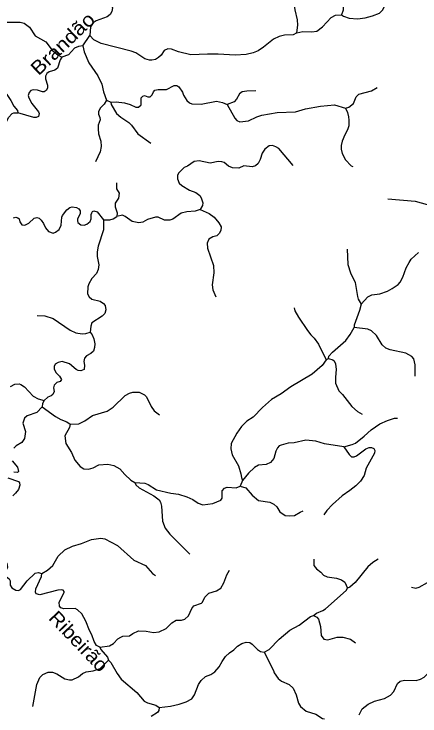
# Model space of a CAD drawing. Extents: x 577 to 602.9, y 7483.8 to 7511.6.
# Drawn here: x 592.922 to 595.283, y 7499.96 to 7504.044 of the extents above; entities that cross this region are included whole.
import ezdxf
from ezdxf.enums import TextEntityAlignment as Align

# ---------------------------------------------------------------- set-up
doc = ezdxf.new("R2010")
doc.units = 0
doc.header["$LTSCALE"] = 0.032
doc.layers.add('61', color=7, linetype='Continuous')
doc.layers.add('7', color=7, linetype='Continuous', lineweight=25)

msp = doc.modelspace()

# ---------------------------------------------------------------- linework, layer by layer
at = {"layer": '7'}
for p, q in [((593.3214, 7503.8597), (593.3623, 7503.9186)), ((593.4596, 7503.5434), (593.4857, 7503.5311)), ((594.738, 7502.032), (594.7511, 7502.0402)), ((594.2517, 7501.3306), (594.2378, 7501.2979))]:
    msp.add_line(p, q, dxfattribs=at)
for points in [[(594.568, 7503.9357), (594.5729, 7503.979), (594.5713, 7504.0101), (594.5565, 7504.0698), (594.5492, 7504.1303), (594.5492, 7504.1572), (594.5606, 7504.2439), (594.5588, 7504.2901)], [(594.7435, 7504.2553), (594.7478, 7504.2414), (594.7887, 7504.1907), (594.8312, 7504.127), (594.8361, 7504.1131), (594.8361, 7504.0673), (594.8263, 7504.0403)], [(593.4857, 7504.1793), (593.4808, 7504.1466), (593.4849, 7504.1049), (593.4939, 7504.0796), (593.4915, 7504.0583), (593.4808, 7504.0412), (593.4645, 7504.0289), (593.4007, 7504.0052), (593.3828, 7503.9938), (593.3664, 7503.9692), (593.3623, 7503.9186)], [(594.8263, 7504.0403), (594.8394, 7504.0322), (594.8721, 7504.0207), (594.9195, 7504.0158), (594.9653, 7504.0224), (595.0069, 7504.033), (595.0478, 7504.0502), (595.0682, 7504.0698), (595.0813, 7504.0984), (595.0862, 7504.1858)], [(592.7904, 7504.0254), (592.867, 7503.9978), (592.9569, 7503.9978), (592.9806, 7503.9913), (593.0125, 7503.9676), (593.0452, 7503.9177), (593.1073, 7503.8818), (593.1441, 7503.8344), (593.1792, 7503.8049), (593.2005, 7503.7943)], [(594.568, 7503.9357), (594.6023, 7503.9423), (594.6538, 7503.9414), (594.6841, 7503.9455), (594.7159, 7503.97), (594.7674, 7504.0248), (594.792, 7504.0371), (594.8263, 7504.0403)], [(594.568, 7503.9357), (594.5451, 7503.9243), (594.4944, 7503.921), (594.4634, 7503.9145), (594.4315, 7503.8973), (594.3735, 7503.8507), (594.3424, 7503.8311), (594.3138, 7503.818), (594.2729, 7503.8082), (594.2075, 7503.8049), (594.1094, 7503.8115), (594.0465, 7503.8115), (593.9509, 7503.8066), (593.8797, 7503.8246), (593.8372, 7503.8409), (593.8168, 7503.8425), (593.7955, 7503.8327), (593.7776, 7503.8057), (593.762, 7503.791), (593.744, 7503.7796), (593.7244, 7503.7755), (593.7105, 7503.7755), (593.6827, 7503.7837), (593.6304, 7503.818), (593.6035, 7503.8286), (593.4285, 7503.8728), (593.3868, 7503.8948), (593.3623, 7503.9186)], [(593.3214, 7503.8597), (593.2961, 7503.8554), (593.274, 7503.8466), (593.2389, 7503.8066), (593.2005, 7503.7943)], [(593.3214, 7503.8597), (593.3304, 7503.8254), (593.3566, 7503.7608), (593.4089, 7503.6856), (593.4334, 7503.6365), (593.4416, 7503.5916), (593.4596, 7503.5434)], [(592.3443, 7503.8202), (592.3937, 7503.7665), (592.4248, 7503.7428), (592.5081, 7503.7085), (592.5376, 7503.7003), (592.5923, 7503.6929), (592.7476, 7503.6807), (592.7738, 7503.6758), (592.7942, 7503.6668), (592.8269, 7503.6431), (592.8547, 7503.6137), (592.9029, 7503.5409), (592.9201, 7503.509), (592.9414, 7503.4837), (592.9446, 7503.4698)], [(593.2005, 7503.7943), (593.1898, 7503.7771), (593.1743, 7503.7289), (593.1588, 7503.7175), (593.1261, 7503.7077), (593.1138, 7503.6979), (593.1048, 7503.6831), (593.1048, 7503.6668), (593.1163, 7503.63), (593.1163, 7503.6137), (593.1089, 7503.5989), (593.0967, 7503.5916), (593.0877, 7503.5908), (593.0591, 7503.6014), (593.0354, 7503.603), (593.0198, 7503.5989), (593.0108, 7503.5883), (593.0051, 7503.5703), (593.0076, 7503.5564), (593.0255, 7503.5237), (593.0648, 7503.4755), (593.0681, 7503.4657), (593.0648, 7503.4477), (593.0509, 7503.442), (593.0378, 7503.442), (592.9446, 7503.4698)], [(593.4857, 7503.5311), (593.5152, 7503.5336), (593.565, 7503.5278), (593.5969, 7503.5188), (593.6296, 7503.5017), (593.6468, 7503.5017), (593.6623, 7503.5156), (593.6623, 7503.5573), (593.6705, 7503.5662), (593.6811, 7503.5695), (593.7007, 7503.563), (593.7138, 7503.563), (593.7261, 7503.5736), (593.7326, 7503.5924), (593.7416, 7503.6006), (593.7604, 7503.6047), (593.8094, 7503.6055), (593.8528, 7503.6284), (593.8683, 7503.6276), (593.8814, 7503.6202), (593.9018, 7503.5891), (593.9075, 7503.572), (593.9263, 7503.5417), (593.9435, 7503.527), (593.9566, 7503.5221), (594.0105, 7503.5205), (594.0988, 7503.5368), (594.134, 7503.5303), (594.1626, 7503.518)], [(594.3289, 7503.5981), (594.2754, 7503.5965), (594.25, 7503.5908), (594.2345, 7503.5793), (594.2157, 7503.5483), (594.2018, 7503.5336), (594.1626, 7503.518)], [(594.8508, 7503.496), (594.8704, 7503.5025), (594.8958, 7503.5237), (594.9121, 7503.563), (594.9277, 7503.5785), (595.0012, 7503.5981), (595.0346, 7503.6165)], [(593.4596, 7503.5434), (593.4465, 7503.5197), (593.4236, 7503.496), (593.4138, 7503.4747), (593.4138, 7503.4624), (593.422, 7503.4428), (593.4236, 7503.4289), (593.4122, 7503.397), (593.4105, 7503.3766), (593.413, 7503.348), (593.4277, 7503.3039), (593.4293, 7503.2728), (593.4236, 7503.2434), (593.3957, 7503.1849)], [(593.4857, 7503.5311), (593.4874, 7503.518), (593.5184, 7503.4657), (593.543, 7503.4436), (593.5904, 7503.4142), (593.6059, 7503.3987), (593.6419, 7503.348), (593.717, 7503.2932)], [(594.1626, 7503.518), (594.2059, 7503.4387), (594.219, 7503.424), (594.2361, 7503.4175), (594.286, 7503.4224), (594.335, 7503.4469), (594.3628, 7503.4559), (594.4527, 7503.4714), (594.559, 7503.4747), (594.6179, 7503.4935), (594.7045, 7503.509), (594.7854, 7503.5156), (594.8508, 7503.496)], [(594.8508, 7503.496), (594.8623, 7503.4706), (594.8672, 7503.4461), (594.8704, 7503.4273), (594.8688, 7503.3938), (594.8614, 7503.3701), (594.8459, 7503.3423), (594.8312, 7503.3047), (594.8255, 7503.2793), (594.8255, 7503.2581), (594.8304, 7503.2327), (594.8508, 7503.1968), (594.8835, 7503.1608), (594.8925, 7503.1581)], [(592.7591, 7503.0619), (592.764, 7503.0832), (592.7525, 7503.1355), (592.7566, 7503.1821), (592.7762, 7503.2115), (592.822, 7503.2532), (592.8424, 7503.2859), (592.8735, 7503.4101), (592.8899, 7503.442), (592.9103, 7503.4649), (592.9201, 7503.469), (592.9446, 7503.4698)], [(594.5461, 7503.1638), (594.4617, 7503.2614), (594.4454, 7503.272), (594.4249, 7503.2785), (594.4061, 7503.2777), (594.38, 7503.2581), (594.3645, 7503.2344), (594.3547, 7503.1984), (594.3424, 7503.1739), (594.3269, 7503.1608), (594.3081, 7503.1559), (594.259, 7503.1608), (594.2296, 7503.1469), (594.1936, 7503.1486), (594.1699, 7503.1592), (594.1446, 7503.1813), (594.1307, 7503.1853), (594.1102, 7503.1862), (594.0637, 7503.1763), (593.9991, 7503.1911), (593.9705, 7503.187), (593.9304, 7503.1592), (593.9124, 7503.151), (593.8806, 7503.1208), (593.8732, 7503.1077), (593.8724, 7503.0848), (593.883, 7503.0611), (593.8977, 7503.0464), (593.9419, 7503.0202), (593.9803, 7503.0055), (594.0032, 7502.9883), (594.0113, 7502.9753), (594.0211, 7502.9458), (594.0187, 7502.9303), (594.004, 7502.9066)], [(593.5184, 7503.0615), (593.5184, 7503.0276), (593.534, 7503.0014), (593.5299, 7502.9736), (593.5103, 7502.9434), (593.5103, 7502.923), (593.5217, 7502.887), (593.5209, 7502.8665)], [(595.0965, 7502.9686), (595.2554, 7502.9556), (595.3731, 7502.923), (595.4148, 7502.9041), (595.4851, 7502.8633), (595.5391, 7502.8093), (595.5611, 7502.7946), (595.5971, 7502.784)], [(592.9193, 7502.8592), (592.9324, 7502.8616), (592.9446, 7502.8592), (592.952, 7502.8527), (592.9561, 7502.8355), (592.9683, 7502.8183), (592.9847, 7502.8151), (593.0076, 7502.8273), (593.0386, 7502.8567), (593.055, 7502.86), (593.0689, 7502.8559), (593.0803, 7502.8445), (593.0942, 7502.8265), (593.1048, 7502.7995), (593.1228, 7502.7783), (593.1498, 7502.7701), (593.1637, 7502.775), (593.1849, 7502.7913), (593.1964, 7502.8167), (593.1997, 7502.8625), (593.2037, 7502.8715), (593.2291, 7502.9041), (593.2462, 7502.918), (593.2593, 7502.923), (593.2863, 7502.918), (593.2986, 7502.9107), (593.3067, 7502.9001), (593.3059, 7502.8845), (593.2912, 7502.851), (593.2904, 7502.8412), (593.2928, 7502.8322), (593.31, 7502.8175), (593.3296, 7502.8159), (593.3452, 7502.8224), (593.3648, 7502.8379), (593.3713, 7502.8535), (593.3713, 7502.878), (593.3746, 7502.8878), (593.3793, 7502.8953), (593.3868, 7502.8992), (593.4065, 7502.8943), (593.4424, 7502.8477)], [(594.004, 7502.9066), (593.9754, 7502.8968), (593.9263, 7502.8935), (593.8944, 7502.8862), (593.8462, 7502.8502), (593.8282, 7502.8445), (593.798, 7502.8453), (593.7604, 7502.8616), (593.7449, 7502.8633), (593.6991, 7502.8494), (593.6705, 7502.833), (593.6484, 7502.8298), (593.6084, 7502.8371), (593.5691, 7502.8657), (593.5528, 7502.8731), (593.5209, 7502.8665)], [(594.004, 7502.9066), (594.0579, 7502.8829), (594.0857, 7502.8616), (594.1143, 7502.8289), (594.1266, 7502.8069), (594.1258, 7502.784), (594.116, 7502.7668), (594.1013, 7502.7546), (594.0775, 7502.7472), (594.0547, 7502.7341), (594.0449, 7502.7104), (594.0465, 7502.6826), (594.0825, 7502.5821), (594.0833, 7502.538), (594.0743, 7502.4685), (594.0784, 7502.439), (594.0966, 7502.3983)], [(593.4424, 7502.8477), (593.4784, 7502.8461), (593.498, 7502.8527), (593.5209, 7502.8665)], [(593.4424, 7502.8477), (593.4432, 7502.7889), (593.4122, 7502.6941), (593.4065, 7502.6614), (593.4056, 7502.6344), (593.4154, 7502.5845), (593.4122, 7502.5584), (593.4016, 7502.5347), (593.3746, 7502.5053), (593.3566, 7502.4742), (593.3517, 7502.457), (593.3501, 7502.4153), (593.3582, 7502.399), (593.3754, 7502.3851), (593.4228, 7502.3737), (593.4424, 7502.3598), (593.4514, 7502.3491), (593.4555, 7502.323), (593.4498, 7502.3017), (593.4351, 7502.287), (593.3754, 7502.247), (593.368, 7502.2282), (593.3656, 7502.193)], [(594.8602, 7502.6765), (594.8639, 7502.5878), (594.8786, 7502.538), (594.9072, 7502.4824), (594.9195, 7502.3998), (594.9244, 7502.3843), (594.9407, 7502.3565)], [(594.9407, 7502.3565), (594.98, 7502.399), (595.0037, 7502.4104), (595.0494, 7502.417), (595.0952, 7502.4325), (595.1222, 7502.4464), (595.1573, 7502.4709), (595.1688, 7502.4832), (595.1835, 7502.5126), (595.2039, 7502.5674), (595.2195, 7502.5984), (595.2325, 7502.6181), (595.2748, 7502.6572)], [(594.5517, 7502.3346), (594.5557, 7502.3173), (594.577, 7502.2797), (594.6293, 7502.202), (594.6493, 7502.1768), (594.6685, 7502.1579), (594.6931, 7502.1227), (594.738, 7502.032)], [(594.9407, 7502.3565), (594.9309, 7502.3197), (594.8999, 7502.2347), (594.9007, 7502.2208)], [(593.0562, 7502.2897), (593.1016, 7502.2878), (593.1498, 7502.2723), (593.2487, 7502.2053), (593.2814, 7502.1897), (593.3182, 7502.1832), (593.3394, 7502.1848), (593.3656, 7502.193)], [(594.7511, 7502.0402), (594.7535, 7502.0532), (594.7748, 7502.0761), (594.8525, 7502.1456), (594.8778, 7502.1799), (594.9007, 7502.2208)], [(595.2562, 7501.9372), (595.2562, 7502.0026), (595.2473, 7502.0385), (595.2366, 7502.0516), (595.2007, 7502.0704), (595.1091, 7502.09), (595.0854, 7502.0998), (595.0633, 7502.1203), (595.0306, 7502.1742), (595.0004, 7502.2012), (594.9791, 7502.2102), (594.9007, 7502.2208)], [(593.3656, 7502.193), (593.377, 7502.1783), (593.386, 7502.1546), (593.3917, 7502.1252), (593.3909, 7502.1039), (593.3836, 7502.0835), (593.3697, 7502.0696), (593.3435, 7502.0557), (593.3329, 7502.0426), (593.328, 7502.0222), (593.3329, 7502.0009), (593.3296, 7501.9764), (593.3116, 7501.9674), (593.2945, 7501.9707), (593.283, 7501.9764), (593.2454, 7502.0083), (593.2029, 7502.023), (593.1784, 7502.0164), (593.1612, 7502.0066), (593.1555, 7501.9936), (593.1563, 7501.9772), (593.167, 7501.9568), (593.1874, 7501.9372), (593.198, 7501.9175), (593.1907, 7501.9069), (593.171, 7501.9004), (593.1555, 7501.8857), (593.1514, 7501.8701), (593.1547, 7501.8481), (593.1482, 7501.8309), (593.1375, 7501.8219), (593.1179, 7501.8145), (593.0967, 7501.7957)], [(594.738, 7502.032), (594.7151, 7501.9985), (594.6571, 7501.9494), (594.5328, 7501.8759), (594.4756, 7501.835), (594.4192, 7501.8007), (594.3669, 7501.7549), (594.3121, 7501.6993), (594.2754, 7501.6756), (594.2451, 7501.6437), (594.2181, 7501.6061), (594.1854, 7501.5448), (594.1822, 7501.5137), (594.1904, 7501.4786), (594.2271, 7501.4157), (594.2418, 7501.3682), (594.2443, 7501.347), (594.2517, 7501.3306)], [(594.7511, 7502.0402), (594.7764, 7502.0328), (594.7846, 7502.0263), (594.7928, 7502.0091), (594.796, 7501.9764), (594.7911, 7501.9306), (594.792, 7501.8955), (594.8108, 7501.8521), (594.8328, 7501.8309), (594.886, 7501.7614), (594.9195, 7501.7312), (594.9465, 7501.7154)], [(592.9021, 7501.8775), (592.9266, 7501.8906), (592.952, 7501.8922), (592.9626, 7501.8889), (592.9839, 7501.8742), (593.0337, 7501.8203), (593.0623, 7501.8056), (593.0967, 7501.7957)], [(593.2479, 7501.6576), (593.2986, 7501.6592), (593.3345, 7501.6764), (593.3787, 7501.7075), (593.4629, 7501.7336), (593.4988, 7501.7565), (593.5683, 7501.8252), (593.5928, 7501.8391), (593.6124, 7501.8448), (593.65, 7501.844), (593.6803, 7501.8284), (593.6917, 7501.8178), (593.7203, 7501.7614), (593.7375, 7501.7361), (593.7689, 7501.7117)], [(593.086, 7501.7581), (593.0542, 7501.7254), (592.9994, 7501.7058), (592.9822, 7501.6919), (592.9732, 7501.6641), (592.9879, 7501.6151), (592.9822, 7501.5742), (592.9667, 7501.5505), (592.934, 7501.5309), (592.9209, 7501.5186)], [(593.0967, 7501.7957), (593.0885, 7501.7778), (593.086, 7501.7581)], [(593.086, 7501.7581), (593.1637, 7501.7017), (593.1939, 7501.6854), (593.2283, 7501.6723), (593.2479, 7501.6576)], [(594.841, 7501.5268), (594.8892, 7501.5391), (594.9089, 7501.5481), (594.9595, 7501.5873), (594.9996, 7501.6249), (595.0496, 7501.6591), (595.0936, 7501.6797), (595.1345, 7501.6919), (595.1524, 7501.6936)], [(593.2479, 7501.6576), (593.2438, 7501.6388), (593.2185, 7501.5906), (593.2242, 7501.5448), (593.2569, 7501.4933), (593.2757, 7501.4483), (593.3059, 7501.4124), (593.328, 7501.3985), (593.3558, 7501.3952), (593.3819, 7501.4034), (593.4154, 7501.4214), (593.4686, 7501.4255), (593.5021, 7501.4181), (593.5381, 7501.3985), (593.5675, 7501.3642), (593.6018, 7501.3315), (593.6255, 7501.3184)], [(594.841, 7501.5268), (594.7274, 7501.5432), (594.6783, 7501.5595), (594.6195, 7501.5652), (594.5516, 7501.5489), (594.5165, 7501.5473), (594.4764, 7501.5366), (594.465, 7501.5309), (594.4552, 7501.5195), (594.4454, 7501.5015), (594.4323, 7501.4582), (594.4143, 7501.4345), (594.3882, 7501.423), (594.3448, 7501.4189), (594.3211, 7501.4058), (594.2852, 7501.3723), (594.2517, 7501.3306)], [(594.841, 7501.5268), (594.8713, 7501.481), (594.8851, 7501.468), (594.9007, 7501.468), (594.9138, 7501.4737), (594.9685, 7501.5146), (594.9881, 7501.5227), (595.0004, 7501.5227), (595.0151, 7501.5154), (595.02, 7501.5039), (595.0192, 7501.4892), (594.971, 7501.4009), (594.9587, 7501.3584), (594.9366, 7501.3266), (594.9097, 7501.2996), (594.8762, 7501.2718), (594.8312, 7501.2415), (594.7748, 7501.1909), (594.7421, 7501.1557), (594.7242, 7501.1303)], [(592.9119, 7501.4451), (592.9414, 7501.4075), (592.9471, 7501.383), (592.9414, 7501.3764), (592.9209, 7501.3781)], [(592.8866, 7501.3462), (592.9487, 7501.3241), (592.9544, 7501.3159), (592.9552, 7501.3028), (592.9487, 7501.2783), (592.9315, 7501.2554), (592.9152, 7501.2407)], [(593.6255, 7501.3184), (593.6304, 7501.3045), (593.65, 7501.2865), (593.7351, 7501.2415), (593.7661, 7501.2178), (593.7735, 7501.2048), (593.78, 7501.1802), (593.7866, 7501.0928), (593.8021, 7501.0527), (593.8291, 7501.0168), (593.9449, 7500.9009)], [(593.6255, 7501.3184), (593.6836, 7501.3151), (593.7032, 7501.3069), (593.7506, 7501.2767), (593.834, 7501.2563), (593.8789, 7501.2497), (593.9271, 7501.235), (593.9615, 7501.2195), (593.9925, 7501.1982), (594.0203, 7501.1892), (594.0775, 7501.1958), (594.1241, 7501.2154), (594.1331, 7501.2276), (594.1331, 7501.2702), (594.1454, 7501.2857), (594.1626, 7501.2906), (594.2141, 7501.2865), (594.2378, 7501.2979)], [(594.2378, 7501.2979), (594.2705, 7501.2865), (594.3064, 7501.244), (594.344, 7501.2146), (594.4094, 7501.2048), (594.4323, 7501.1933), (594.4503, 7501.177), (594.4691, 7501.1484), (594.4985, 7501.1263), (594.523, 7501.1238), (594.5541, 7501.1271), (594.586, 7501.1467), (594.6031, 7501.1527)], [(593.0836, 7500.7887), (593.1171, 7500.8091), (593.1473, 7500.8353), (593.1792, 7500.8892), (593.2185, 7500.926), (593.2626, 7500.9473), (593.3149, 7500.9628), (593.3721, 7500.9865), (593.4261, 7500.9947), (593.4498, 7500.9906), (593.5242, 7500.9522), (593.6198, 7500.8664), (593.686, 7500.8353), (593.7277, 7500.7895), (593.7453, 7500.7782)], [(592.8482, 7500.8647), (592.8678, 7500.8598), (592.8809, 7500.8492), (592.8841, 7500.8263), (592.8694, 7500.7928), (592.8686, 7500.7781), (592.8931, 7500.7576), (592.8988, 7500.7454), (592.9005, 7500.7217), (592.9095, 7500.7053), (592.9332, 7500.6922), (592.9471, 7500.6898), (592.9593, 7500.6955), (592.9978, 7500.7462), (593.0452, 7500.7903), (593.0623, 7500.7952), (593.0836, 7500.7887)], [(594.6662, 7500.8729), (594.6653, 7500.8345), (594.6808, 7500.8157), (594.707, 7500.7961), (594.7225, 7500.7789), (594.7429, 7500.7691), (594.7985, 7500.7625), (594.8263, 7500.7519), (594.8459, 7500.7388), (594.8623, 7500.7037)], [(595.0406, 7500.8726), (595.0086, 7500.8525), (594.9791, 7500.8271), (594.9056, 7500.7372), (594.8762, 7500.7094), (594.8623, 7500.7037)], [(593.4212, 7500.3596), (593.4016, 7500.3702), (593.3877, 7500.3923), (593.3746, 7500.4323), (593.3607, 7500.4577), (593.3394, 7500.5116), (593.3157, 7500.5541), (593.2912, 7500.5778), (593.2773, 7500.5852), (593.2127, 7500.5827), (593.1947, 7500.5893), (593.1858, 7500.5982), (593.1841, 7500.6219), (593.2144, 7500.6792), (593.2144, 7500.6841), (593.2078, 7500.6914), (593.1972, 7500.6947), (593.1759, 7500.6922), (593.073, 7500.6645), (593.0501, 7500.6702), (593.0468, 7500.68), (593.0493, 7500.6988), (593.0819, 7500.7715), (593.0836, 7500.7887)], [(593.4212, 7500.3596), (593.4776, 7500.3677), (593.5013, 7500.3816), (593.5266, 7500.4078), (593.543, 7500.4192), (593.5544, 7500.4241), (593.5936, 7500.4266), (593.6133, 7500.4397), (593.6468, 7500.4544), (593.6909, 7500.4527), (593.7334, 7500.4454), (593.7661, 7500.4495), (593.8062, 7500.4683), (593.8397, 7500.5026), (593.8658, 7500.5181), (593.8961, 7500.5173), (593.9165, 7500.5222), (593.9361, 7500.5427), (593.9566, 7500.586), (593.9688, 7500.6007), (594.0122, 7500.6154), (594.0187, 7500.6219), (594.0326, 7500.6506), (594.0547, 7500.6751), (594.0996, 7500.6873), (594.1241, 7500.7045), (594.1421, 7500.7348), (594.1601, 7500.7805), (594.1748, 7500.8083)], [(595.2339, 7500.7089), (595.2587, 7500.7037), (595.2791, 7500.7086), (595.3274, 7500.7372), (595.3919, 7500.7462), (595.414, 7500.7544), (595.4287, 7500.7674), (595.4459, 7500.7748), (595.4631, 7500.7789), (595.4884, 7500.7756), (595.5023, 7500.7634), (595.5096, 7500.7421), (595.5113, 7500.7045), (595.5195, 7500.6555), (595.5342, 7500.6244), (595.5538, 7500.6007), (595.5734, 7500.5631)], [(594.6636, 7500.5443), (594.6808, 7500.5574), (594.7184, 7500.5729), (594.7331, 7500.5827), (594.8533, 7500.689), (594.8623, 7500.7037)], [(594.3767, 7500.331), (594.4053, 7500.3457), (594.4642, 7500.4062), (594.5263, 7500.4585), (594.5811, 7500.4879), (594.6473, 7500.5394), (594.6636, 7500.5443)], [(594.6636, 7500.5443), (594.6832, 7500.5353), (594.6931, 7500.523), (594.7053, 7500.4814), (594.7078, 7500.4282), (594.7241, 7500.4062), (594.747, 7500.4037), (594.8026, 7500.4176), (594.8353, 7500.4176), (594.8794, 7500.407), (594.9089, 7500.3849)], [(593.7661, 7500.0089), (593.8323, 7500.0163), (593.883, 7500.0285), (593.9239, 7500.0416), (593.9558, 7500.0596), (593.9713, 7500.0825), (593.995, 7500.1429), (594.0105, 7500.1667), (594.0359, 7500.1887), (594.0661, 7500.2002), (594.0906, 7500.2165), (594.116, 7500.2451), (594.1323, 7500.277), (594.1528, 7500.3064), (594.1748, 7500.3277), (594.201, 7500.344), (594.2214, 7500.3653), (594.2468, 7500.3816), (594.2729, 7500.3898), (594.2942, 7500.3874), (594.3081, 7500.3784), (594.3391, 7500.3457), (594.3563, 7500.3359), (594.3767, 7500.331)], [(593.4212, 7500.3596), (593.4261, 7500.3465), (593.4661, 7500.3015), (593.471, 7500.2844)], [(594.3767, 7500.331), (594.4315, 7500.2247), (594.4348, 7500.2116), (594.4585, 7500.1773), (594.4773, 7500.1626), (594.5222, 7500.1421), (594.5459, 7500.1225), (594.5639, 7500.0825), (594.5762, 7500.0351), (594.5884, 7500.0146), (594.6211, 7499.9876), (594.6767, 7499.9697), (594.7159, 7499.946), (594.7278, 7499.9426)], [(594.9287, 7499.9661), (594.9473, 7500.0007), (594.9816, 7500.0285), (595.0184, 7500.0457), (595.0764, 7500.062), (595.1124, 7500.0808), (595.132, 7500.1021), (595.1524, 7500.1479), (595.1688, 7500.1626), (595.1925, 7500.1683), (595.2603, 7500.1667), (595.2865, 7500.1748), (595.3069, 7500.1863), (595.3527, 7500.228), (595.3846, 7500.2476), (595.4238, 7500.259), (595.4704, 7500.2607), (595.5146, 7500.2721), (595.5685, 7500.2983), (595.5898, 7500.326), (595.6053, 7500.3383)], [(593.0322, 7500.0147), (593.0542, 7500.1438), (593.0721, 7500.1838), (593.0901, 7500.2002), (593.1212, 7500.2141), (593.1449, 7500.2141), (593.1719, 7500.2059), (593.2176, 7500.1765), (593.2438, 7500.1699), (593.2601, 7500.1707), (593.2969, 7500.1871), (593.3206, 7500.2075), (593.3411, 7500.2173), (593.3828, 7500.2231), (593.4236, 7500.2361), (593.471, 7500.2844)], [(593.471, 7500.2844), (593.4849, 7500.2713), (593.5217, 7500.2075), (593.5462, 7500.1732), (593.637, 7500.0972), (593.6795, 7500.0465), (593.6983, 7500.0359), (593.7473, 7500.0228), (593.7661, 7500.0089)], [(593.7661, 7500.0089), (593.7637, 7499.9925), (593.7563, 7499.9803), (593.7195, 7499.9558)]]:
    msp.add_lwpolyline(points, dxfattribs=at)

# ---------------------------------------------------------------- texts
at = {"layer": '61'}
for s, rotation, width, p in [('Brandão', 43.856, 1.15, (593.2326, 7503.8432)), ('Ribeirão', 313.661, 1.1, (593.269, 7500.3667))]:
    msp.add_text(s, height=0.08, rotation=rotation, dxfattribs=dict(at, width=width)).set_placement(p, align=Align.CENTER)

doc.saveas('drawing.dxf')
